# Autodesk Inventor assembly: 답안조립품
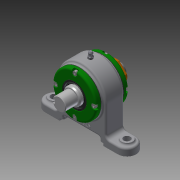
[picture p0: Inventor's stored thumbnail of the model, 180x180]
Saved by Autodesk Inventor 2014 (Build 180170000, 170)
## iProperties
Created: 2019-05
Part Number: 답안조립품
Document SubType Name: Weldment
Designer: kh
Weld Material: Welded Aluminum-6061
Author: kh
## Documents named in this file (13)
- C:\Users\kh\Desktop\490504v1054\답안조립품.iam
- C:\Users\kh\Desktop\490504v1054\본체.ipt
- C:\Users\kh\Desktop\490504v1054\개스킷.ipt
- C:\Users\kh\Desktop\490504v1054\그리스니플 M6.ipt
- 그리스니플  M6.ipt
- C:\Users\kh\Desktop\490504v1054\그리스니플개스킷.ipt
- C:\Users\kh\Desktop\490504v1054\베어링너트.ipt
- C:\Users\kh\Desktop\490504v1054\볼트 M4.ipt
- C:\Users\kh\Desktop\490504v1054\앵귤러 볼 베어링 7205.ipt
- C:\Users\kh\Desktop\490504v1054\오일 실 28 40 5 B.ipt
- C:\Users\kh\Desktop\490504v1054\축.ipt
- C:\Users\kh\Desktop\490504v1054\칼라.ipt
- C:\Users\kh\Desktop\490504v1054\커버.ipt
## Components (4 placed, 3 different names)
1. 개스킷:1
2. 그리스니플  M6:1
3. 그리스니플개스킷:1
4. 개스킷:2
